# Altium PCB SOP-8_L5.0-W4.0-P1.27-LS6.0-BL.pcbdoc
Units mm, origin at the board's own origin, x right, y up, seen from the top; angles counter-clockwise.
Board outline 18.02 x 20.27 mm, 2 copper layers (Top Layer, Bottom Layer), stack 0 mm thick; 1 components, 0 nets, 8 pads, 0 vias.
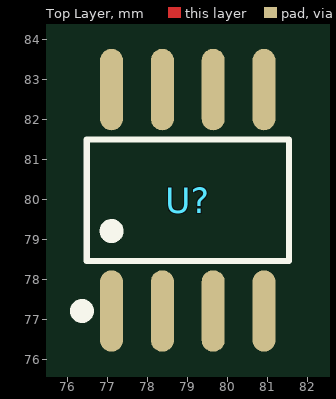
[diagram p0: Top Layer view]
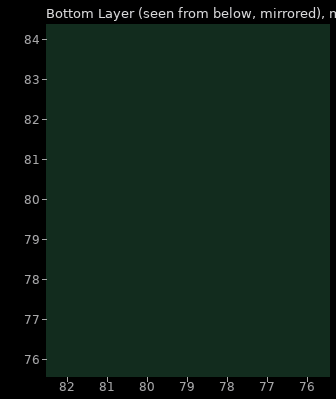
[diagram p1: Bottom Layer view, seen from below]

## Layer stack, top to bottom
Top Layer: signal copper (thickness not stored)
Bottom Layer: signal copper (thickness not stored)

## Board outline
87.871,69.85 69.85,69.85 69.85,90.121 87.871,90.121

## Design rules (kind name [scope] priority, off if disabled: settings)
PasteMaskExpansion "Paste Mask Expansion" [All] p1: expansion=0
SolderMaskExpansion "Solder Mask Expansion" [IsVia] p1: expansion=-25.4 istentingtop=TRUE
SolderMaskExpansion "Solder Mask Expansion" [All] p2: expansion=0.051 istentingtop=FALSE

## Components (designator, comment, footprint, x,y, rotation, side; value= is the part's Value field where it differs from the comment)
U? "" SOP-8_L5.0-W4.0-P1.27-LS6.0-BL 78.995,79.986 r0 top

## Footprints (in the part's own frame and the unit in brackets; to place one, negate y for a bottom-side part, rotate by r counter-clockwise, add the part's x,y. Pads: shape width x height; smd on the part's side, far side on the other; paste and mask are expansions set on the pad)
SOP-8_L5.0-W4.0-P1.27-LS6.0-BL [mm]
  oval 0.574x2.036 smd: 1(-1.905,-2.768) 2(-0.635,-2.768) 3(0.635,-2.768) 4(1.905,-2.768) 5(1.905,2.768) 6(0.635,2.768) 7(-0.635,2.768) 8(-1.905,2.768)
  silkscreen extent -2.79,-2.92 2.53,1.52

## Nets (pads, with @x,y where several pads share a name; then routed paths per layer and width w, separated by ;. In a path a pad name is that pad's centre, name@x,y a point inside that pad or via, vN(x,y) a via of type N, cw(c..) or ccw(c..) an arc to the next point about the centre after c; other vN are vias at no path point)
pads on no net: U?.1 U?.2 U?.3 U?.4 U?.5 U?.6 U?.7 U?.8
